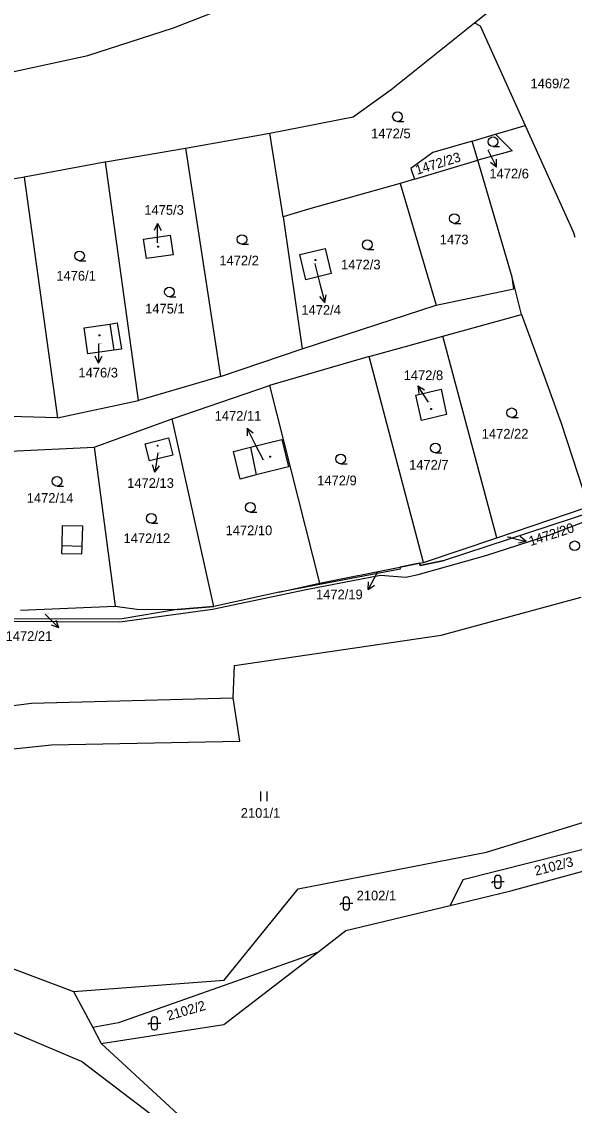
# Model space of a CAD drawing. Extents: x -805730 to -804640, y -1150889 to -1150366.
# Drawn here: x -805194.5 to -805108.7, y -1150727 to -1150558.7 of the extents above; entities that cross this region are included whole.
import ezdxf

# ---------------------------------------------------------------- set-up
doc = ezdxf.new("R2010")
doc.units = 0
for name, color, linetype in [('Default', 7, 'Continuous'), ('kilometráž - vrstava 7', 7, 'Continuous'), ('kn_celek - Cisla parcel pomocna', 7, 'Continuous'), ('kn_celek - Cisla pozemkovych parcel', 7, 'Continuous'), ('kn_celek - Cisla stavebnich parcel', 7, 'Continuous'), ('kn_celek - Hranice parcel', 7, 'Continuous'), ('kn_celek - Vnitrni kresby', 7, 'Continuous'), ('kn_celek - Znacky budov', 7, 'Continuous'), ('kn_celek - Znacky kultur', 7, 'Continuous'), ('plochy - SZDC', 7, 'Continuous'), ('PSR_C2_2_trasa_Vimperk - Kabelová trasa', 7, 'Continuous')]:
    doc.layers.add(name, color=color, linetype=linetype)

# ---------------------------------------------------------------- blocks, each defined once
blk = doc.blocks.new('304')
at = {"layer": 'Default'}
blk.add_line((-0.1, 0), (9.9, 0), dxfattribs=at)
blk.add_circle((-0.1, 7.5), 7.5, dxfattribs=at)
blk = doc.blocks.new('306')
at = {"layer": 'Default'}
for p, q in [((-5.2, 0), (-5.2, 15)), ((4.8, 0), (4.8, 15))]:
    blk.add_line(p, q, dxfattribs=at)
blk = doc.blocks.new('316')
at = {"layer": 'Default'}
for p, q in [((0.5, 20), (-0.5, 20)), ((-8.3, 10), (-10, 8.1)), ((-5, 10), (-8.3, 10)), ((-5, 15.5), (-5, 4.5)), ((-5, 10), (5, 10)), ((-0.5, 0), (0.5, 0)), ((5, 4.5), (5, 15.5)), ((10, 10), (5, 10))]:
    blk.add_line(p, q, dxfattribs=at)
for centre, start, end in [((-0.5, 15.5), 90, 180), ((0.5, 15.5), 0, 90), ((-0.5, 4.5), 180, 270), ((0.5, 4.5), 270, 0)]:
    blk.add_arc(centre, 4.5, start, end, dxfattribs=at)
blk = doc.blocks.new('402')
at = {"layer": 'Default'}
for p, q in [((-0.8, 0.8), (0.7, 0.8)), ((-0.8, 0.8), (-0.8, -0.7)), ((0.7, 0.8), (0.7, -0.7)), ((0.7, -0.7), (-0.8, -0.7))]:
    blk.add_line(p, q, dxfattribs=at)
blk = doc.blocks.new('Z61')
at = {"layer": 'Default'}
for p, q in [((0, 0), (30, 0)), ((30, 0), (19.2, 5.3)), ((30, 0), (19.2, -5.3))]:
    blk.add_line(p, q, dxfattribs=at)

msp = doc.modelspace()

# ---------------------------------------------------------------- linework, layer by layer
at = {"layer": 'kilometráž - vrstava 7'}
msp.add_circle((-805108.67, -1150640.09), 0.75, dxfattribs=at)
at = {"layer": 'kn_celek - Cisla parcel pomocna'}
for p, q in [((-805149.02, -1150596.3), (-805148.22, -1150599.38)), ((-805157, -1150626.77), (-805158.17, -1150624.49))]:
    msp.add_line(p, q, dxfattribs=at)
at = {"layer": 'kn_celek - Hranice parcel'}
for p, q in [((-805170.94, -1150559.63), (-805157.79, -1150554.48)), ((-805124.23, -1150558.85), (-805121.16, -1150556.44)), ((-805184.24, -1150563.91), (-805170.94, -1150559.63)), ((-805137.16, -1150569.23), (-805124.23, -1150558.85)), ((-805124.23, -1150558.85), (-805123.35, -1150559.31)), ((-805123.35, -1150559.31), (-805116.35, -1150574.79)), ((-805197.9, -1150566.86), (-805184.24, -1150563.91)), ((-805143.08, -1150573.46), (-805137.16, -1150569.23)), ((-805156, -1150576), (-805143.08, -1150573.46)), ((-805120.93, -1150576.14), (-805116.35, -1150574.79)), ((-805116.35, -1150574.79), (-805108.82, -1150591.44)), ((-805169.07, -1150578.3), (-805156, -1150576)), ((-805153.92, -1150588.97), (-805156, -1150576)), ((-805124.58, -1150577.22), (-805120.93, -1150576.14)), ((-805120.93, -1150576.14), (-805118.36, -1150578.76)), ((-805181.51, -1150580.47), (-805169.12, -1150578.31)), ((-805169.12, -1150578.31), (-805169.07, -1150578.3)), ((-805169.07, -1150578.3), (-805163.68, -1150613.78)), ((-805124.58, -1150577.22), (-805130.69, -1150579.02)), ((-805123.7, -1150580.21), (-805124.58, -1150577.22)), ((-805130.69, -1150579.02), (-805134.09, -1150581.46)), ((-805118.36, -1150578.76), (-805123.7, -1150580.21)), ((-805181.63, -1150580.5), (-805194.17, -1150582.84)), ((-805181.51, -1150580.47), (-805181.63, -1150580.5)), ((-805176.39, -1150617.53), (-805181.51, -1150580.47)), ((-805134.09, -1150581.46), (-805133.51, -1150583.16)), ((-805133.51, -1150583.16), (-805123.7, -1150580.21)), ((-805118.39, -1150598.36), (-805123.7, -1150580.21)), ((-805194.37, -1150582.88), (-805206.79, -1150584.83)), ((-805194.17, -1150582.84), (-805194.37, -1150582.88)), ((-805194.17, -1150582.84), (-805188.96, -1150620.19)), ((-805133.51, -1150583.16), (-805135.74, -1150583.81)), ((-805135.74, -1150583.81), (-805150, -1150587.78)), ((-805135.74, -1150583.81), (-805130.67, -1150600.93)), ((-805150, -1150587.78), (-805153.92, -1150588.97)), ((-805153.92, -1150588.97), (-805150.96, -1150609.51)), ((-805108.82, -1150591.44), (-805108.63, -1150592.17)), ((-805175.62, -1150592.44), (-805171.46, -1150591.84)), ((-805175.17, -1150595.46), (-805175.62, -1150592.44)), ((-805171.46, -1150591.84), (-805171.01, -1150594.89)), ((-805171.01, -1150594.89), (-805175.17, -1150595.46)), ((-805151.32, -1150594.85), (-805147.39, -1150593.91)), ((-805150.39, -1150598.75), (-805151.32, -1150594.85)), ((-805147.39, -1150593.91), (-805146.46, -1150597.81)), ((-805146.46, -1150597.81), (-805150.39, -1150598.75)), ((-805118.12, -1150600.19), (-805118.39, -1150598.36)), ((-805116.91, -1150604.14), (-805118.39, -1150598.36)), ((-805130.18, -1150602.69), (-805118.12, -1150600.19)), ((-805130.67, -1150600.93), (-805130.18, -1150602.69)), ((-805150.96, -1150609.51), (-805130.18, -1150602.69)), ((-805129.15, -1150607.51), (-805116.91, -1150604.14)), ((-805116.91, -1150604.14), (-805113.43, -1150613.57)), ((-805184.82, -1150606.24), (-805180.87, -1150605.65)), ((-805184.28, -1150610.26), (-805184.82, -1150606.24)), ((-805180.87, -1150605.65), (-805179.73, -1150605.48)), ((-805179.73, -1150605.48), (-805179.03, -1150609.54)), ((-805140.56, -1150610.66), (-805129.15, -1150607.51)), ((-805120.75, -1150638.84), (-805129.15, -1150607.51)), ((-805180.2, -1150609.7), (-805184.28, -1150610.26)), ((-805179.03, -1150609.54), (-805180.2, -1150609.7)), ((-805163.68, -1150613.78), (-805150.96, -1150609.51)), ((-805140.56, -1150610.66), (-805156.07, -1150615.2)), ((-805132.12, -1150642.68), (-805140.56, -1150610.66)), ((-805113.43, -1150613.57), (-805110.75, -1150621.04)), ((-805163.68, -1150613.78), (-805176.39, -1150617.53)), ((-805171.14, -1150620.35), (-805156.07, -1150615.2)), ((-805156.07, -1150615.2), (-805148.29, -1150645.9)), ((-805133.32, -1150616.71), (-805129.41, -1150615.78)), ((-805132.45, -1150620.65), (-805133.32, -1150616.71)), ((-805129.41, -1150615.78), (-805128.54, -1150619.71)), ((-805188.96, -1150620.19), (-805176.39, -1150617.53)), ((-805188.96, -1150620.19), (-805202.04, -1150619.89)), ((-805183.26, -1150624.76), (-805171.14, -1150620.35)), ((-805164.69, -1150649.54), (-805171.14, -1150620.35)), ((-805128.54, -1150619.71), (-805132.45, -1150620.65)), ((-805110.75, -1150621.04), (-805106.53, -1150634.03)), ((-805175.35, -1150624.23), (-805171.71, -1150623.34)), ((-805171.71, -1150623.34), (-805171.06, -1150625.99)), ((-805159.01, -1150624.79), (-805154.14, -1150623.59)), ((-805154.14, -1150623.59), (-805153.1, -1150627.82)), ((-805196.37, -1150625.39), (-805183.26, -1150624.76)), ((-805183.26, -1150624.76), (-805180.04, -1150649.49)), ((-805174.7, -1150626.88), (-805175.35, -1150624.23)), ((-805161.65, -1150625.43), (-805159.01, -1150624.79)), ((-805160.61, -1150629.72), (-805161.65, -1150625.43)), ((-805171.06, -1150625.99), (-805174.7, -1150626.88)), ((-805153.1, -1150627.82), (-805158.11, -1150629.09)), ((-805158.11, -1150629.09), (-805160.61, -1150629.72)), ((-805105.89, -1150634.79), (-805128.92, -1150642.38)), ((-805120.75, -1150638.84), (-805107.03, -1150634.2)), ((-805132.12, -1150642.68), (-805120.75, -1150638.84)), ((-805135.75, -1150643.74), (-805153.67, -1150647.14)), ((-805148.29, -1150645.9), (-805135.82, -1150643.41)), ((-805135.82, -1150643.41), (-805132.75, -1150642.8)), ((-805135.82, -1150643.41), (-805135.75, -1150643.74)), ((-805132.75, -1150642.8), (-805132.12, -1150642.68)), ((-805132.75, -1150642.8), (-805132.67, -1150643.17)), ((-805132.67, -1150643.17), (-805128.92, -1150642.38)), ((-805154.57, -1150647.29), (-805164.69, -1150649.54)), ((-805154.57, -1150647.29), (-805148.29, -1150645.9)), ((-805153.67, -1150647.14), (-805154.57, -1150647.29)), ((-805129.38, -1150653.98), (-805107.63, -1150648.08)), ((-805194.7, -1150650.11), (-805180.04, -1150649.49)), ((-805180.04, -1150649.49), (-805176.67, -1150649.94)), ((-805170.38, -1150650), (-805178.93, -1150651.45)), ((-805176.67, -1150649.94), (-805170.38, -1150650)), ((-805170.38, -1150650), (-805170.32, -1150649.99)), ((-805170.32, -1150649.99), (-805164.69, -1150649.54)), ((-805178.93, -1150651.45), (-805208.17, -1150651.53)), ((-805161.49, -1150658.69), (-805129.38, -1150653.98)), ((-805161.69, -1150663.73), (-805161.49, -1150658.69)), ((-805193.03, -1150664.54), (-805161.69, -1150663.73)), ((-805160.65, -1150670.45), (-805161.69, -1150663.73)), ((-805220.59, -1150668.04), (-805193.03, -1150664.54)), ((-805189.9, -1150671), (-805160.65, -1150670.45)), ((-805218.5, -1150674.08), (-805189.9, -1150671)), ((-805122.34, -1150687.69), (-805093.75, -1150678.86)), ((-805090.83, -1150683.08), (-805126.05, -1150692)), ((-805118.57, -1150693.67), (-805089.07, -1150685.63)), ((-805151.58, -1150693.36), (-805122.34, -1150687.69)), ((-805126.05, -1150692), (-805127.99, -1150695.94)), ((-805163.1, -1150707.54), (-805151.58, -1150693.36)), ((-805127.99, -1150695.94), (-805118.57, -1150693.67)), ((-805144.18, -1150699.84), (-805127.99, -1150695.94)), ((-805208.12, -1150701.15), (-805186.47, -1150709.31)), ((-805148.6, -1150703.25), (-805144.18, -1150699.84)), ((-805148.6, -1150703.25), (-805179.51, -1150714.21)), ((-805163.12, -1150714.45), (-805148.6, -1150703.25)), ((-805186.47, -1150709.31), (-805163.1, -1150707.54)), ((-805185.27, -1150720.22), (-805211.82, -1150708.9)), ((-805186.47, -1150709.31), (-805183.51, -1150714.93)), ((-805179.51, -1150714.21), (-805183.51, -1150714.93)), ((-805182.21, -1150717.39), (-805163.12, -1150714.45)), ((-805183.51, -1150714.93), (-805182.21, -1150717.39)), ((-805182.21, -1150717.39), (-805165.75, -1150732.51)), ((-805167.17, -1150733.91), (-805185.27, -1150720.22))]:
    msp.add_line(p, q, dxfattribs=at)
at = {"layer": 'kn_celek - Vnitrni kresby'}
for p, q in [((-805180.87, -1150605.65), (-805180.2, -1150609.7)), ((-805159.01, -1150624.79), (-805158.11, -1150629.09)), ((-805188.25, -1150640.05), (-805188.19, -1150636.96)), ((-805188.19, -1150636.96), (-805185.08, -1150637)), ((-805185.08, -1150637), (-805185.2, -1150640.13)), ((-805188.28, -1150641.34), (-805188.25, -1150640.05)), ((-805188.25, -1150640.05), (-805185.2, -1150640.13)), ((-805185.2, -1150640.13), (-805185.26, -1150641.41)), ((-805185.26, -1150641.41), (-805188.28, -1150641.34))]:
    msp.add_line(p, q, dxfattribs=at)
at = {"layer": 'plochy - SZDC'}
for p, q in [((-805105.89, -1150634.79), (-805128.92, -1150642.38)), ((-805135.75, -1150643.74), (-805153.67, -1150647.14)), ((-805132.75, -1150642.8), (-805135.82, -1150643.41)), ((-805135.82, -1150643.41), (-805135.75, -1150643.74)), ((-805132.67, -1150643.17), (-805132.75, -1150642.8)), ((-805128.92, -1150642.38), (-805132.67, -1150643.17)), ((-805154.57, -1150647.29), (-805164.69, -1150649.54)), ((-805153.67, -1150647.14), (-805154.57, -1150647.29)), ((-805129.38, -1150653.98), (-805107.63, -1150648.08)), ((-805170.38, -1150650), (-805178.93, -1150651.45)), ((-805170.32, -1150649.99), (-805170.38, -1150650)), ((-805164.69, -1150649.54), (-805170.32, -1150649.99)), ((-805178.93, -1150651.45), (-805208.17, -1150651.53)), ((-805161.49, -1150658.69), (-805129.38, -1150653.98)), ((-805161.69, -1150663.73), (-805161.49, -1150658.69)), ((-805193.03, -1150664.54), (-805161.69, -1150663.73)), ((-805220.59, -1150668.04), (-805193.03, -1150664.54))]:
    msp.add_line(p, q, dxfattribs=at)
at = {"layer": 'PSR_C2_2_trasa_Vimperk - Kabelová trasa'}
for points in [[(-805122.45, -1150641.59), (-805112.53, -1150638.37), (-805102.25, -1150634.46), (-805084.03, -1150627.11), (-805075.4, -1150623.5), (-805060.17, -1150617.08), (-805047.9, -1150611.92), (-805039.79, -1150608.5), (-804989.01, -1150587.76)], [(-805214.1, -1150652.28), (-805208.19, -1150651.74), (-805179.31, -1150651.91), (-805164.88, -1150649.95), (-805150.36, -1150646.9), (-805138.79, -1150644.66), (-805134.9, -1150644.97), (-805132.95, -1150644.53), (-805122.45, -1150641.59)]]:
    msp.add_lwpolyline(points, dxfattribs=at)

# ---------------------------------------------------------------- block references
at = {"layer": 'kn_celek - Cisla parcel pomocna'}
for p, xscale, yscale, rotation in [((-805122.12, -1150578.57), 0.1, 0.09999999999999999, -63.43496999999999), ((-805173.42, -1150593.04), 0.1, 0.10000000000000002, 90.00000000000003), ((-805148.22, -1150599.38), 0.10000000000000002, 0.1, -75.4704), ((-805182.58, -1150608.7), 0.1, 0.10000000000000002, -90.00000000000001), ((-805131.37, -1150617.78), 0.1, 0.09999999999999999, 122.82858000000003), ((-805158.17, -1150624.49), 0.1, 0.10000000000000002, 117.11268), ((-805173.39, -1150625.67), 0.1, 0.10000000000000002, -98.53083000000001), ((-805119.11, -1150638.7), 0.1, 0.10000000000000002, -14.036219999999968), ((-805139.31, -1150644.25), 0.1, 0.10000000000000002, -117.89720999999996), ((-805190.89, -1150650.7), 0.1, 0.10000000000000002, -44.999999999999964)]:
    msp.add_blockref('Z61', p, dxfattribs=dict(at, xscale=xscale, yscale=yscale, rotation=rotation))
at = {"layer": 'kn_celek - Znacky budov', "xscale": 0.1, "yscale": 0.10000000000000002}
for p in [(-805173.38, -1150593.61), (-805148.94, -1150595.68), (-805182.45, -1150607.41), (-805130.98, -1150618.83), (-805173.44, -1150624.53), (-805155.96, -1150626.25)]:
    msp.add_blockref('402', p, dxfattribs=at)
at = {"layer": 'kn_celek - Znacky kultur', "xscale": 0.1, "yscale": 0.10000000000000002}
for name, p in [('304', (-805136.17, -1150574.18)), ('304', (-805121.33, -1150578.08)), ('304', (-805127.34, -1150590)), ('304', (-805160.32, -1150593.26)), ('304', (-805140.84, -1150594.06)), ('304', (-805185.54, -1150595.8)), ('304', (-805171.58, -1150601.4)), ('304', (-805118.44, -1150620.18)), ('304', (-805130.27, -1150625.65)), ('304', (-805144.99, -1150627.34)), ('304', (-805189.04, -1150630.81)), ('304', (-805159.02, -1150634.86)), ('304', (-805174.38, -1150636.58)), ('306', (-805156.87, -1150679.74)), ('316', (-805120.59, -1150693.29)), ('316', (-805144.13, -1150696.65)), ('316', (-805173.93, -1150715.27))]:
    msp.add_blockref(name, p, dxfattribs=at)

# ---------------------------------------------------------------- texts
at = {"layer": 'kn_celek - Cisla parcel pomocna'}
for s, p in [('1469/2', (-805115.52, -1150569.02)), ('1472/6', (-805121.9, -1150583.02)), ('1475/3', (-805175.49, -1150588.67)), ('1472/4', (-805151.1, -1150604.21)), ('1476/3', (-805185.72, -1150613.94)), ('1472/8', (-805135.22, -1150614.35)), ('1472/11', (-805164.57, -1150620.65)), ('1472/13', (-805178.15, -1150631.09)), ('1472/19', (-805148.83, -1150648.39)), ('1472/21', (-805197.03, -1150654.86))]:
    msp.add_text(s, height=1.5, dxfattribs=at).set_placement(p)
msp.add_text('1472/20', height=1.5, rotation=18, dxfattribs=at).set_placement((-805115.5, -1150640.15))
at = {"layer": 'kn_celek - Cisla pozemkovych parcel'}
for s, height, p in [('1472/5', 1.5, (-805140.27, -1150576.78)), ('1472/6', 0.1, (-805122.12, -1150578.54)), ('1473', 1.5, (-805129.61, -1150593.26)), ('1472/2', 1.5, (-805163.84, -1150596.52)), ('1472/3', 1.5, (-805144.94, -1150597.15)), ('1476/1', 1.5, (-805189.16, -1150598.89)), ('1475/1', 1.5, (-805175.36, -1150604)), ('1472/22', 1.5, (-805123.09, -1150623.43)), ('1472/7', 1.5, (-805134.37, -1150628.25)), ('1472/9', 1.5, (-805148.64, -1150630.68)), ('1472/14', 1.5, (-805193.75, -1150633.41)), ('1472/10', 1.5, (-805162.87, -1150638.44)), ('1472/12', 1.5, (-805178.72, -1150639.67)), ('1472/20', 0.1, (-805119.11, -1150638.67)), ('1472/19', 0.1, (-805139.31, -1150644.22)), ('1472/21', 0.1, (-805190.89, -1150650.67)), ('2101/1', 1.5, (-805160.51, -1150682.34)), ('2102/1', 1.5, (-805142.52, -1150695.17))]:
    msp.add_text(s, height=height, dxfattribs=at).set_placement(p)
for s, rotation, p in [('1472/23', 17.1, (-805133.15, -1150582.47)), ('2102/3', 14.4, (-805114.69, -1150691.35)), ('2102/2', 16.2, (-805171.74, -1150713.85))]:
    msp.add_text(s, height=1.5, rotation=rotation, dxfattribs=at).set_placement(p)
at = {"layer": 'kn_celek - Cisla stavebnich parcel'}
for s, p in [('1475/3', (-805173.42, -1150593.01)), ('1472/4', (-805149.29, -1150596.27)), ('1476/3', (-805182.58, -1150608.67)), ('1472/8', (-805131.37, -1150617.75)), ('1472/13', (-805173.39, -1150625.64)), ('1472/11', (-805157.29, -1150626.75))]:
    msp.add_text(s, height=0.1, dxfattribs=at).set_placement(p)

doc.saveas('drawing.dxf')
